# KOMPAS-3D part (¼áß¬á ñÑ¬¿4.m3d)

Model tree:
1. Эскиз:1
2. Операция выдавливания:24
     Толщина стенки 2 = 10; Расстояние 1 = 0.6
3. Эскиз:22
4. Операция выдавливания:25
     Толщина стенки 1 = 6; Толщина стенки 2 = 6; Расстояние 1 = 0.6
5. Эскиз:23
6. Операция выдавливания:26
     Толщина стенки 1 = 6; Толщина стенки 2 = 6; Расстояние 1 = 0.6
7. Эскиз:24
8. Операция выдавливания:27
     Толщина стенки 1 = 6; Толщина стенки 2 = 6; Расстояние 1 = 0.6
9. Эскиз:25
10. Вырезать элемент выдавливания:10
     Расстояние 1 = 10
